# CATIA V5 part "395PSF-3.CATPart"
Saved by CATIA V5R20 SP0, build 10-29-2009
Part number: 395PSF-3
Source: Unknown
Property "ARTICLENO": "395PSF-3"
Property "BOMINFO": "395PSF-3"
Property "CODE": "395PSF-3"
Property "D": "43.000"
Property "D1": "53.000"
Property "H": "6.000"
Property "L": "233.000"
Property "L1": "8.000"
Property "L2": "195.000"
Property "L3": "12.000"
Property "L4": "8.000"
Property "LINA": "395PSF-3"
Property "MAXLOAD": "5000 Kg"
Property "MDW": "10000 Kg"
Property "NB": "395PSF-3"
Property "NBSYN": "$CODE."
Property "NN": "395PSF"
Property "NT": "FIAT Lifting Pins"
Property "SUPPLIER": "CF"
Bounding box of the stored display mesh (mm): x 0 to 233, y -27.5 to 26.5, z -26.5 to 26.5
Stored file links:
  C:\Users\Utente\Desktop\3D files 395PSF\395PSF-3.CATPart
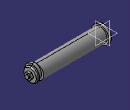
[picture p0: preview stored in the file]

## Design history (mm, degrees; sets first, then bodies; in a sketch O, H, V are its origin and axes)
Body1 "Geometry.1" (main body)
  Solid1 "395PSF-3.catpart": solid without history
